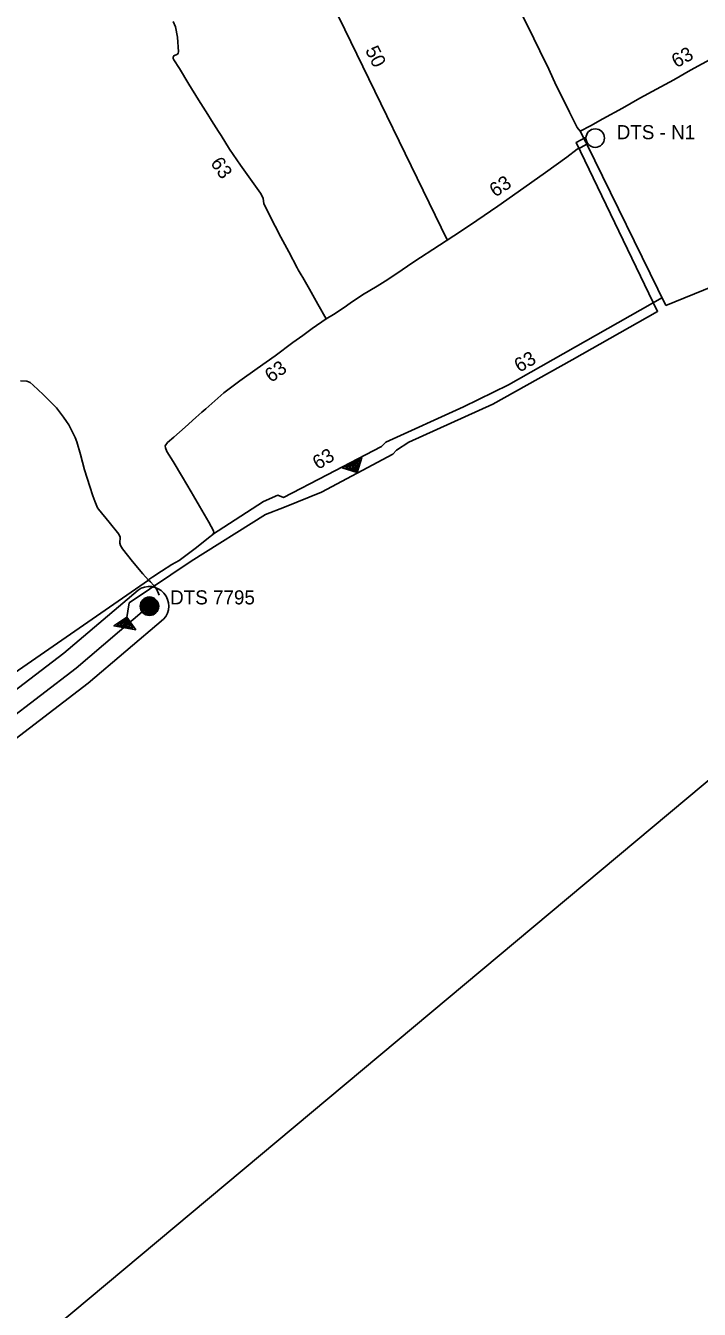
# Model space of a CAD drawing. Extents: x -444841 to -429545, y -1135312 to -1129851.
# Drawn here: x -442033 to -441650, y -1130962 to -1130233 of the extents above; entities that cross this region are included whole.
import ezdxf

# ---------------------------------------------------------------- set-up
doc = ezdxf.new("R2010")
doc.units = 0
for name, color, linetype in [('Vrstva 10', 7, 'Continuous'), ('Vrstva 11', 7, 'Continuous'), ('Vrstva 13', 7, 'Continuous'), ('Vrstva 15', 7, 'Continuous'), ('Vrstva 18', 7, 'Continuous'), ('Vrstva 19', 7, 'Continuous'), ('Vrstva 21', 7, 'Continuous'), ('Vrstva 27', 7, 'Continuous'), ('Vrstva 30', 7, 'Continuous'), ('Vrstva 35', 7, 'Continuous'), ('Vrstva 38', 7, 'Continuous'), ('Vrstva 59', 7, 'Continuous')]:
    doc.layers.add(name, color=color, linetype=linetype)

msp = doc.modelspace()

# ---------------------------------------------------------------- linework, layer by layer
at = {"layer": 'Vrstva 10'}
msp.add_lwpolyline([(-442545.2, -1131006.71), (-442443.5, -1130934.6), (-442365.65, -1130877.08), (-442301.93, -1130826.75), (-442234.54, -1130772.43), (-442143.45, -1130703.1), (-442064.73, -1130644.42), (-442003.9, -1130597.89), (-441963.63, -1130563.69)], dxfattribs=at)
at = {"layer": 'Vrstva 11'}
for radius in [5.25, 4.55, 3.85, 3.15, 2.45, 1.75, 1.05, 0.35]:
    msp.add_circle((-441962.15, -1130562.69), radius, dxfattribs=at)
at = {"layer": 'Vrstva 15'}
for points in [[(-441968.62, -1130553.5), (-442010.81, -1130589.32), (-442071.36, -1130635.64), (-442150.07, -1130694.32), (-442241.33, -1130763.77), (-442308.79, -1130818.15), (-442372.32, -1130868.34), (-442449.95, -1130925.69), (-442551.7, -1130997.84)], [(-442511.53, -1130996.32), (-442437.05, -1130943.51), (-442358.97, -1130885.82), (-442295.07, -1130835.35), (-442227.76, -1130781.09), (-442136.83, -1130711.89), (-442058.1, -1130653.2), (-441997, -1130606.45), (-441954.08, -1130570.1)]]:
    msp.add_lwpolyline(points, dxfattribs=at)
msp.add_arc((-441962.27, -1130562.6), 11.1, 317.50257, 124.90759, dxfattribs=at)
at = {"layer": 'Vrstva 18'}
msp.add_lwpolyline([(-441975.84, -1130573.79), (-441973.68, -1130560.84), (-441938.52, -1130537.09), (-441896.26, -1130510.56), (-441885.41, -1130506.39), (-441864.4, -1130498), (-441823.77, -1130476.32), (-441821.75, -1130474.03), (-441814.82, -1130469.54), (-441767.01, -1130447.94), (-441721.98, -1130422.65), (-441673.35, -1130395.2), (-441719.61, -1130299.27), (-441714.03, -1130296.36)], dxfattribs=at)
for points in [[(-441852.62, -1130484.13), (-441841.47, -1130478.26), (-441844.12, -1130486.77)], [(-441850.8, -1130483.96), (-441842.64, -1130479.67), (-441844.58, -1130485.9)], [(-441848.98, -1130483.79), (-441843.81, -1130481.07), (-441845.04, -1130485.02)], [(-441847.16, -1130483.63), (-441844.98, -1130482.48), (-441845.5, -1130484.14)], [(-441969.98, -1130576.19), (-441982.36, -1130573.88), (-441975.01, -1130568.84)], [(-441971.51, -1130575.19), (-441980.57, -1130573.5), (-441975.2, -1130569.82)], [(-441973.04, -1130574.2), (-441978.78, -1130573.12), (-441975.38, -1130570.79)], [(-441974.58, -1130573.2), (-441976.99, -1130572.75), (-441975.56, -1130571.76)]]:
    msp.add_lwpolyline(points, close=True, dxfattribs=at)
at = {"layer": 'Vrstva 19'}
msp.add_circle((-441708.82, -1130296.8), 5.25, dxfattribs=at)
at = {"layer": 'Vrstva 27'}
for points in [[(-441717.27, -1130292.86), (-441719.01, -1130290.81), (-441723.46, -1130282.16), (-441727.48, -1130274.01), (-441730.95, -1130266.93), (-441735.22, -1130257.64), (-441740.28, -1130247.26), (-441747.14, -1130233.17), (-441752.52, -1130222.43)], [(-441875, -1130375.9), (-441875.85, -1130374.44), (-441877.54, -1130371.53), (-441878.19, -1130370.4), (-441882.99, -1130361.39), (-441887.45, -1130353.09), (-441890.79, -1130346.73), (-441897.17, -1130334.22), (-441897.6, -1130330.98), (-441898.99, -1130328.04), (-441904.68, -1130320.13), (-441910.36, -1130312.1), (-441916.67, -1130303.05), (-441921.47, -1130295.33), (-441922.95, -1130293.06), (-441926.92, -1130286.8), (-441929.05, -1130283.43), (-441934.31, -1130275.02), (-441939.72, -1130266.21), (-441945.13, -1130257.34), (-441948.31, -1130252.38), (-441948.62, -1130251.54), (-441948.65, -1130250.74), (-441948.33, -1130250.1), (-441946.23, -1130249.08), (-441945.83, -1130248.59), (-441945.56, -1130247.81), (-441946.17, -1130239.54), (-441947.32, -1130233.56), (-441948.66, -1130230.5)], [(-441717.27, -1130292.86), (-441711.43, -1130289.9), (-441704.43, -1130285.91), (-441693.31, -1130279.87), (-441683.39, -1130274.1), (-441674.01, -1130269.07), (-441664.14, -1130263.67), (-441654.56, -1130258.26), (-441641.31, -1130250.95), (-441637.91, -1130248.58)], [(-441861.78, -1130399.43), (-441857.59, -1130397.07), (-441851.4, -1130393.02), (-441848.02, -1130390.65), (-441841.09, -1130385.91), (-441832.77, -1130380.81), (-441828.11, -1130377.99), (-441822.05, -1130374.02), (-441811.85, -1130367.16), (-441797.37, -1130357.55), (-441785.41, -1130349.76), (-441776.03, -1130343.66), (-441764.23, -1130335.39), (-441752.64, -1130327.24), (-441736.98, -1130316.37), (-441724.95, -1130307.61), (-441718.98, -1130303.12), (-441717.06, -1130302.21), (-441713.63, -1130300.31), (-441714.15, -1130299.15), (-441717.27, -1130292.86)], [(-441861.78, -1130399.43), (-441866.47, -1130391.13), (-441871.12, -1130382.6), (-441875, -1130375.9)], [(-441861.78, -1130399.43), (-441869.64, -1130404.98), (-441875, -1130408.84)], [(-441875, -1130408.84), (-441880.61, -1130412.89), (-441890.77, -1130420.38), (-441900.93, -1130427.64), (-441910.76, -1130434.69), (-441919.79, -1130441.56), (-441930.15, -1130450.57), (-441932.39, -1130452.56), (-441935.81, -1130455.59), (-441941.85, -1130460.99), (-441948.31, -1130466.76), (-441951.85, -1130469.75), (-441953.17, -1130471.53), (-441953.03, -1130472.79), (-441952.28, -1130474.75), (-441948.6, -1130480.41), (-441943.45, -1130489.31), (-441938.49, -1130497.66), (-441937.13, -1130500)], [(-441994.27, -1130500), (-441996.11, -1130494.73), (-441999.09, -1130485.29), (-442001.43, -1130476.55), (-442003.49, -1130469.28), (-442004.29, -1130466.9), (-442005.11, -1130465.27), (-442008.04, -1130459.62), (-442009.22, -1130457.82), (-442010.94, -1130455.32), (-442014.99, -1130450.03), (-442022.65, -1130442.38), (-442028.22, -1130437.2), (-442030.04, -1130435.62), (-442031.87, -1130434.82), (-442035.46, -1130434.73)], [(-441937.13, -1130500), (-441933.73, -1130505.86), (-441928.31, -1130515.03), (-441925.69, -1130519.86), (-441925.57, -1130520.89), (-441926.1, -1130521.93), (-441928.55, -1130523.78), (-441935.46, -1130529.33), (-441945.34, -1130536.72), (-441949.36, -1130538.97), (-441955.35, -1130542.79), (-441960.27, -1130546.03), (-441962.44, -1130547.59), (-441962.74, -1130547.8), (-441965.95, -1130544.37), (-441971.72, -1130537.34), (-441977.54, -1130530.04), (-441978.58, -1130528.29), (-441978.93, -1130526.93), (-441978.82, -1130523.52), (-441979.49, -1130521.79), (-441985.14, -1130514.87), (-441991.07, -1130507.53), (-441991.6, -1130506.77), (-441992.03, -1130505.89), (-441993.24, -1130502.96), (-441994.27, -1130500)], [(-441956.63, -1130556.34), (-441958.03, -1130553.11), (-441959.86, -1130550.64), (-441961.52, -1130548.79), (-441962.74, -1130547.8)]]:
    msp.add_lwpolyline(points, dxfattribs=at)
at = {"layer": 'Vrstva 35'}
for p, q in [((-441713.63, -1130300.31), (-441668.67, -1130391.9)), ((-442109.22, -1130649.14), (-441962.74, -1130547.8))]:
    msp.add_line(p, q, dxfattribs=at)
for points in [[(-441668.67, -1130391.9), (-441615.56, -1130370.21), (-441594.82, -1130359.43), (-441553.79, -1130315.76), (-441550.83, -1130312.8), (-441511.74, -1130253.59), (-441504.05, -1130247.07), (-441423.51, -1130202.07), (-441415.22, -1130194.37), (-441411.67, -1130185.78), (-441450.75, -1130136.04), (-441478.58, -1130098.15), (-441485.69, -1130076.83), (-441489.84, -1130057.88)], [(-441792.9, -1130354.63), (-441854.53, -1130228.08), (-441882.43, -1130176.46)], [(-441861.11, -1130488.08), (-441830.31, -1130471.9), (-441827.83, -1130469.42), (-441783.73, -1130449.52), (-441758.08, -1130436.98), (-441670.62, -1130387.42)], [(-441926.31, -1130521.97), (-441897.34, -1130503.3), (-441889.2, -1130499.59), (-441885.99, -1130500.9), (-441861.11, -1130488.08)]]:
    msp.add_lwpolyline(points, dxfattribs=at)
at = {"layer": 'Vrstva 59'}
msp.add_lwpolyline([(-441161.73, -1130257.99), (-444840.51, -1133333.5)], dxfattribs=at)

# ---------------------------------------------------------------- texts
at = {"layer": 'Vrstva 13'}
msp.add_text('DTS 7795', height=8, dxfattribs=at).set_placement((-441950.4, -1130561.67))
at = {"layer": 'Vrstva 21'}
msp.add_text('DTS - N1', height=8, dxfattribs=at).set_placement((-441696.56, -1130297.42))
at = {"layer": 'Vrstva 30'}
for rotation, p in [(28.88544, (-441662.64, -1130257.18)), (304.88566, (-441927.81, -1130310.99)), (33.07772, (-441765.65, -1130330.64)), (35.54835, (-441893.01, -1130435.96))]:
    msp.add_text('63', height=8, rotation=rotation, dxfattribs=at).set_placement(p)
at = {"layer": 'Vrstva 38'}
for s, rotation, p in [('50', 296.23818, (-441839.73, -1130246.79)), ('63', 29.74672, (-441751.95, -1130430.16)), ('63', 31.39027, (-441866.38, -1130485.43))]:
    msp.add_text(s, height=8, rotation=rotation, dxfattribs=at).set_placement(p)

doc.saveas('drawing.dxf')
